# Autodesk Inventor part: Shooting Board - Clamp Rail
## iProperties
Created: 2010-08
Part Number: Shooting Board - Clamp Rail
Material: Default
Document SubType Name: Modeling
Designer: Paul Munford
Density: 1 g/cm^3
Author: Paul Munford
Thickness: 19 mm
Width: 19 mm
Length: 1 mm
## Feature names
1. Extrusion1
